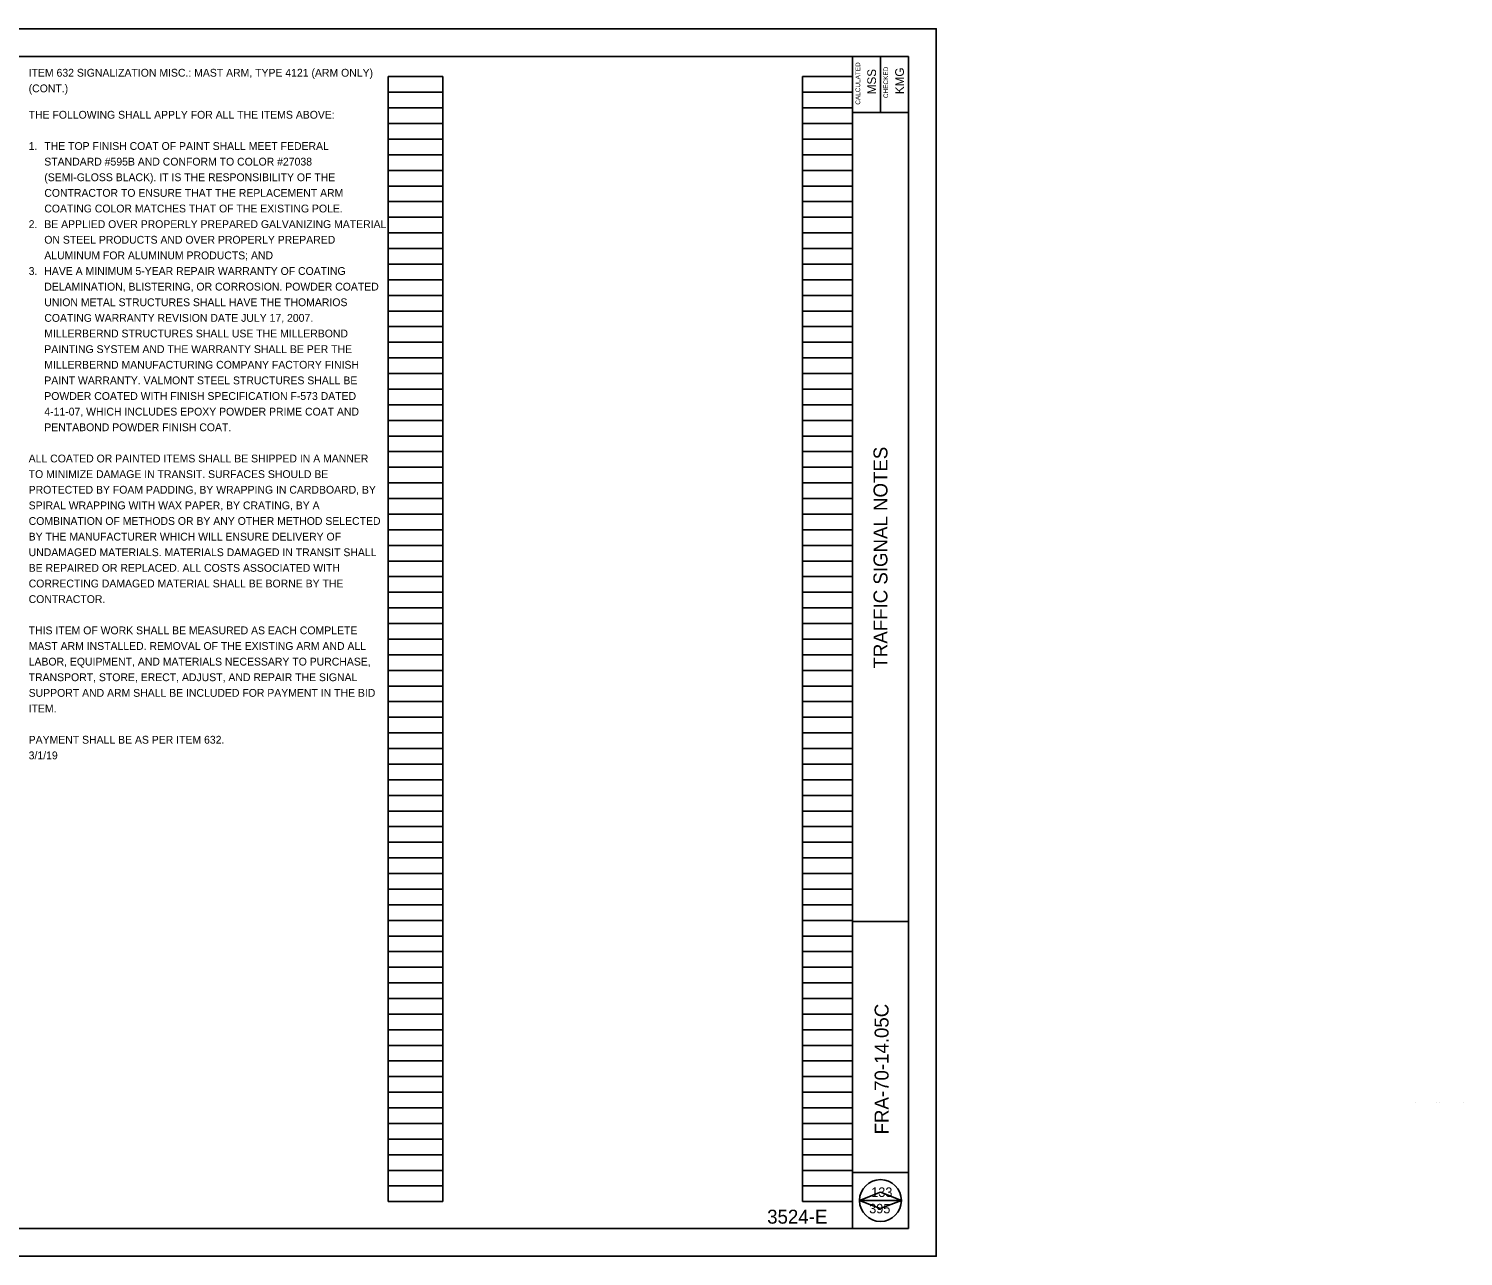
# Model space of a CAD drawing. Extents: x -15.1 to 53.7, y -46.4 to 36.
# Drawn here: x 17.23 to 42.94, y -7.51 to 14.49 of the extents above; entities that cross this region are included whole.
import ezdxf

# ---------------------------------------------------------------- set-up
doc = ezdxf.new("R2010")
doc.units = 0
for name, color, linetype in [('Default', 7, 'Continuous'), ('Level 63', 7, 'Continuous'), ('PF_P_Text', 7, 'Continuous'), ('SC_Scratch1', 7, 'Continuous'), ('SH_Cut_Line', 7, 'Continuous'), ('SH_Text', 7, 'Continuous')]:
    doc.layers.add(name, color=color, linetype=linetype)

# ---------------------------------------------------------------- blocks, each defined once
blk = doc.blocks.new('POINT_DISPLAY')
at = {"layer": 'Default'}
blk.add_line((0, 0), (0, 0), dxfattribs=at)

msp = doc.modelspace()

# ---------------------------------------------------------------- linework, layer by layer
at = {"layer": 'Level 63'}
msp.add_line((32.119, -6.508), (32.869, -6.508), dxfattribs=at)
msp.add_circle((32.494, -6.508), 0.375, dxfattribs=at)
at = {"layer": 'PF_P_Text'}
for p, q in [((31.994, -7.008), (31.994, 13.992)), ((32.494, 13.992), (32.494, 12.992)), ((31.994, 12.992), (32.994, 12.992)), ((31.994, -1.508), (32.994, -1.508)), ((31.994, -6.008), (32.994, -6.008))]:
    msp.add_line(p, q, dxfattribs=at)
msp.add_lwpolyline([(1.494, 13.992), (32.994, 13.992), (32.994, -7.008), (1.494, -7.008)], close=True, dxfattribs=at)
at = {"layer": 'SC_Scratch1'}
for p, q in [((23.674, -6.528), (23.674, 13.632)), ((23.674, 13.632), (24.654, 13.632)), ((24.654, -6.528), (24.654, 13.632)), ((31.094, -6.528), (31.094, 13.632)), ((31.094, 13.632), (31.994, 13.632)), ((31.994, -6.528), (31.994, 13.632)), ((23.674, 13.352), (24.654, 13.352)), ((31.094, 13.352), (31.994, 13.352)), ((23.674, 13.072), (24.654, 13.072)), ((31.094, 13.072), (31.994, 13.072)), ((23.674, 12.792), (24.654, 12.792)), ((31.094, 12.792), (31.994, 12.792)), ((23.674, 12.512), (24.654, 12.512)), ((31.094, 12.512), (31.994, 12.512)), ((23.674, 12.232), (24.654, 12.232)), ((31.094, 12.232), (31.994, 12.232)), ((23.674, 11.952), (24.654, 11.952)), ((31.094, 11.952), (31.994, 11.952)), ((23.674, 11.672), (24.654, 11.672)), ((31.094, 11.672), (31.994, 11.672)), ((23.674, 11.392), (24.654, 11.392)), ((31.094, 11.392), (31.994, 11.392)), ((23.674, 11.112), (24.654, 11.112)), ((31.094, 11.112), (31.994, 11.112)), ((23.674, 10.832), (24.654, 10.832)), ((31.094, 10.832), (31.994, 10.832)), ((23.674, 10.552), (24.654, 10.552)), ((31.094, 10.552), (31.994, 10.552)), ((23.674, 10.272), (24.654, 10.272)), ((31.094, 10.272), (31.994, 10.272)), ((23.674, 9.992), (24.654, 9.992)), ((31.094, 9.992), (31.994, 9.992)), ((23.674, 9.712), (24.654, 9.712)), ((31.094, 9.712), (31.994, 9.712)), ((23.674, 9.432), (24.654, 9.432)), ((31.094, 9.432), (31.994, 9.432)), ((23.674, 9.152), (24.654, 9.152)), ((31.094, 9.152), (31.994, 9.152)), ((23.674, 8.872), (24.654, 8.872)), ((31.094, 8.872), (31.994, 8.872)), ((23.674, 8.592), (24.654, 8.592)), ((31.094, 8.592), (31.994, 8.592)), ((23.674, 8.312), (24.654, 8.312)), ((31.094, 8.312), (31.994, 8.312)), ((23.674, 8.032), (24.654, 8.032)), ((31.094, 8.032), (31.994, 8.032)), ((23.674, 7.752), (24.654, 7.752)), ((31.094, 7.752), (31.994, 7.752)), ((23.674, 7.472), (24.654, 7.472)), ((31.094, 7.472), (31.994, 7.472)), ((23.674, 7.192), (24.654, 7.192)), ((31.094, 7.192), (31.994, 7.192)), ((23.674, 6.912), (24.654, 6.912)), ((31.094, 6.912), (31.994, 6.912)), ((23.674, 6.632), (24.654, 6.632)), ((31.094, 6.632), (31.994, 6.632)), ((23.674, 6.352), (24.654, 6.352)), ((31.094, 6.352), (31.994, 6.352)), ((23.674, 6.072), (24.654, 6.072)), ((31.094, 6.072), (31.994, 6.072)), ((23.674, 5.792), (24.654, 5.792)), ((31.094, 5.792), (31.994, 5.792)), ((23.674, 5.512), (24.654, 5.512)), ((31.094, 5.512), (31.994, 5.512)), ((23.674, 5.232), (24.654, 5.232)), ((31.094, 5.232), (31.994, 5.232)), ((23.674, 4.952), (24.654, 4.952)), ((31.094, 4.952), (31.994, 4.952)), ((23.674, 4.672), (24.654, 4.672)), ((31.094, 4.672), (31.994, 4.672)), ((23.674, 4.392), (24.654, 4.392)), ((31.094, 4.392), (31.994, 4.392)), ((23.674, 4.112), (24.654, 4.112)), ((31.094, 4.112), (31.994, 4.112)), ((23.674, 3.832), (24.654, 3.832)), ((31.094, 3.832), (31.994, 3.832)), ((23.674, 3.552), (24.654, 3.552)), ((31.094, 3.552), (31.994, 3.552)), ((23.674, 3.272), (24.654, 3.272)), ((31.094, 3.272), (31.994, 3.272)), ((23.674, 2.992), (24.654, 2.992)), ((31.094, 2.992), (31.994, 2.992)), ((23.674, 2.712), (24.654, 2.712)), ((31.094, 2.712), (31.994, 2.712)), ((23.674, 2.432), (24.654, 2.432)), ((31.094, 2.432), (31.994, 2.432)), ((23.674, 2.152), (24.654, 2.152)), ((31.094, 2.152), (31.994, 2.152)), ((23.674, 1.872), (24.654, 1.872)), ((31.094, 1.872), (31.994, 1.872)), ((23.674, 1.592), (24.654, 1.592)), ((31.094, 1.592), (31.994, 1.592)), ((23.674, 1.312), (24.654, 1.312)), ((31.094, 1.312), (31.994, 1.312)), ((23.674, 1.032), (24.654, 1.032)), ((31.094, 1.032), (31.994, 1.032)), ((23.674, 0.752), (24.654, 0.752)), ((31.094, 0.752), (31.994, 0.752)), ((23.674, 0.472), (24.654, 0.472)), ((31.094, 0.472), (31.994, 0.472)), ((23.674, 0.192), (24.654, 0.192)), ((31.094, 0.192), (31.994, 0.192)), ((23.674, -0.088), (24.654, -0.088)), ((31.094, -0.088), (31.994, -0.088)), ((23.674, -0.368), (24.654, -0.368)), ((31.094, -0.368), (31.994, -0.368)), ((23.674, -0.648), (24.654, -0.648)), ((31.094, -0.648), (31.994, -0.648)), ((23.674, -0.928), (24.654, -0.928)), ((31.094, -0.928), (31.994, -0.928)), ((23.674, -1.208), (24.654, -1.208)), ((31.094, -1.208), (31.994, -1.208)), ((23.674, -1.488), (24.654, -1.488)), ((31.094, -1.488), (31.994, -1.488)), ((23.674, -1.768), (24.654, -1.768)), ((31.094, -1.768), (31.994, -1.768)), ((23.674, -2.048), (24.654, -2.048)), ((31.094, -2.048), (31.994, -2.048)), ((23.674, -2.328), (24.654, -2.328)), ((31.094, -2.328), (31.994, -2.328)), ((23.674, -2.608), (24.654, -2.608)), ((31.094, -2.608), (31.994, -2.608)), ((23.674, -2.888), (24.654, -2.888)), ((31.094, -2.888), (31.994, -2.888)), ((23.674, -3.168), (24.654, -3.168)), ((31.094, -3.168), (31.994, -3.168)), ((23.674, -3.448), (24.654, -3.448)), ((31.094, -3.448), (31.994, -3.448)), ((23.674, -3.728), (24.654, -3.728)), ((31.094, -3.728), (31.994, -3.728)), ((23.674, -4.008), (24.654, -4.008)), ((31.094, -4.008), (31.994, -4.008)), ((23.674, -4.288), (24.654, -4.288)), ((31.094, -4.288), (31.994, -4.288)), ((23.674, -4.568), (24.654, -4.568)), ((31.094, -4.568), (31.994, -4.568)), ((23.674, -4.848), (24.654, -4.848)), ((31.094, -4.848), (31.994, -4.848)), ((23.674, -5.128), (24.654, -5.128)), ((31.094, -5.128), (31.994, -5.128)), ((23.674, -5.408), (24.654, -5.408)), ((31.094, -5.408), (31.994, -5.408)), ((23.674, -5.688), (24.654, -5.688)), ((31.094, -5.688), (31.994, -5.688)), ((23.674, -5.968), (24.654, -5.968)), ((31.094, -5.968), (31.994, -5.968)), ((23.674, -6.248), (24.654, -6.248)), ((31.094, -6.248), (31.994, -6.248)), ((32.119, -6.508), (32.495, -6.36)), ((32.495, -6.36), (32.869, -6.508)), ((23.674, -6.528), (24.654, -6.528)), ((31.094, -6.528), (31.994, -6.528)), ((32.49, -6.654), (32.119, -6.508)), ((32.869, -6.508), (32.49, -6.654))]:
    msp.add_line(p, q, dxfattribs=at)
at = {"layer": 'SH_Cut_Line'}
msp.add_lwpolyline([(-0.506, -7.508), (33.494, -7.508), (33.494, 14.492), (-0.506, 14.492)], close=True, dxfattribs=at)

# ---------------------------------------------------------------- block references
at = {"layer": 'Default', "xscale": 3.9370000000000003, "yscale": 3.9370000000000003}
for p in [(42.08, -4.749), (42.08, -4.749), (42.446, -4.749), (42.507, -4.749), (42.935, -4.749)]:
    msp.add_blockref('POINT_DISPLAY', p, dxfattribs=at)

# ---------------------------------------------------------------- texts
at = {"layer": 'Level 63'}
for s, p in [('CALCULATED', (32.13, 13.129)), ('CHECKED', (32.63, 13.248))]:
    msp.add_text(s, height=0.0833, rotation=90, dxfattribs=at).set_placement(p)
at = {"layer": 'SH_Text'}
for s, height, rotation, p in [('ITEM 632 SIGNALIZATION MISC.: MAST ARM, TYPE 4121 (ARM ONLY) ', 0.14, 0, (17.234, 13.632)), ('MSS', 0.156, 90, (32.414, 13.317)), ('KMG', 0.156, 90, (32.914, 13.319)), ('(CONT.)', 0.14, 0, (17.234, 13.352)), ('TRAFFIC SIGNAL NOTES', 0.25, 90, (32.619, 3.025)), ('FRA-70-14.05C', 0.25, 90, (32.639, -5.324)), ('3524-E', 0.25, 359.9999, (30.464, -6.923))]:
    msp.add_text(s, height=height, rotation=rotation, dxfattribs=at).set_placement(p)
for s, height, p in [('THE FOLLOWING SHALL APPLY FOR ALL THE ITEMS ABOVE:', 0.14, (17.234, 12.879)), ('1.', 0.14, (17.234, 12.319)), ('THE TOP FINISH COAT OF PAINT SHALL MEET FEDERAL ', 0.14, (17.514, 12.319)), ('STANDARD #595B AND CONFORM TO COLOR #27038 ', 0.14, (17.514, 12.039)), ('(SEMI-GLOSS BLACK). IT IS THE RESPONSIBILITY OF THE ', 0.14, (17.514, 11.759)), ('CONTRACTOR TO ENSURE THAT THE REPLACEMENT ARM ', 0.14, (17.514, 11.479)), ('COATING COLOR MATCHES THAT OF THE EXISTING POLE. ', 0.14, (17.514, 11.199)), ('2.', 0.14, (17.234, 10.919)), ('BE APPLIED OVER PROPERLY PREPARED GALVANIZING MATERIAL ', 0.14, (17.514, 10.919)), ('ON STEEL PRODUCTS AND OVER PROPERLY PREPARED ', 0.14, (17.514, 10.639)), ('ALUMINUM FOR ALUMINUM PRODUCTS; AND', 0.14, (17.514, 10.359)), ('3.', 0.14, (17.234, 10.079)), ('HAVE A MINIMUM 5-YEAR REPAIR WARRANTY OF COATING ', 0.14, (17.514, 10.079)), ('DELAMINATION, BLISTERING, OR CORROSION. POWDER COATED ', 0.14, (17.514, 9.799)), ('UNION METAL STRUCTURES SHALL HAVE THE THOMARIOS ', 0.14, (17.514, 9.519)), ('COATING WARRANTY REVISION DATE JULY 17, 2007. ', 0.14, (17.514, 9.239)), ('MILLERBERND STRUCTURES SHALL USE THE MILLERBOND ', 0.14, (17.514, 8.959)), ('PAINTING SYSTEM AND THE WARRANTY SHALL BE PER THE ', 0.14, (17.514, 8.679)), ('MILLERBERND MANUFACTURING COMPANY FACTORY FINISH ', 0.14, (17.514, 8.399)), ('PAINT WARRANTY. VALMONT STEEL STRUCTURES SHALL BE ', 0.14, (17.514, 8.119)), ('POWDER COATED WITH FINISH SPECIFICATION F-573 DATED ', 0.14, (17.514, 7.839)), ('4-11-07, WHICH INCLUDES EPOXY POWDER PRIME COAT AND ', 0.14, (17.514, 7.559)), ('PENTABOND POWDER FINISH COAT.', 0.14, (17.514, 7.279)), ('ALL COATED OR PAINTED ITEMS SHALL BE SHIPPED IN A MANNER ', 0.14, (17.234, 6.719)), ('TO MINIMIZE DAMAGE IN TRANSIT. SURFACES SHOULD BE ', 0.14, (17.234, 6.439)), ('PROTECTED BY FOAM PADDING, BY WRAPPING IN CARDBOARD, BY ', 0.14, (17.234, 6.159)), ('SPIRAL WRAPPING WITH WAX PAPER, BY CRATING, BY A ', 0.14, (17.234, 5.879)), ('COMBINATION OF METHODS OR BY ANY OTHER METHOD SELECTED ', 0.14, (17.234, 5.599)), ('BY THE MANUFACTURER WHICH WILL ENSURE DELIVERY OF ', 0.14, (17.234, 5.319)), ('UNDAMAGED MATERIALS. MATERIALS DAMAGED IN TRANSIT SHALL ', 0.14, (17.234, 5.039)), ('BE REPAIRED OR REPLACED. ALL COSTS ASSOCIATED WITH ', 0.14, (17.234, 4.759)), ('CORRECTING DAMAGED MATERIAL SHALL BE BORNE BY THE ', 0.14, (17.234, 4.479)), ('CONTRACTOR.', 0.14, (17.234, 4.199)), ('THIS ITEM OF WORK SHALL BE MEASURED AS EACH COMPLETE ', 0.14, (17.234, 3.639)), ('MAST ARM INSTALLED. REMOVAL OF THE EXISTING ARM AND ALL ', 0.14, (17.234, 3.359)), ('LABOR, EQUIPMENT, AND MATERIALS NECESSARY TO PURCHASE, ', 0.14, (17.234, 3.079)), ('TRANSPORT, STORE, ERECT, ADJUST, AND REPAIR THE SIGNAL ', 0.14, (17.234, 2.799)), ('SUPPORT AND ARM SHALL BE INCLUDED FOR PAYMENT IN THE BID ', 0.14, (17.234, 2.519)), ('ITEM.  ', 0.14, (17.234, 2.239)), ('PAYMENT SHALL BE AS PER ITEM 632.', 0.14, (17.234, 1.679)), ('3/1/19', 0.14, (17.234, 1.399)), ('133', 0.17, (32.328, -6.444)), ('395', 0.17, (32.292, -6.738))]:
    msp.add_text(s, height=height, dxfattribs=at).set_placement(p)

doc.saveas('drawing.dxf')
